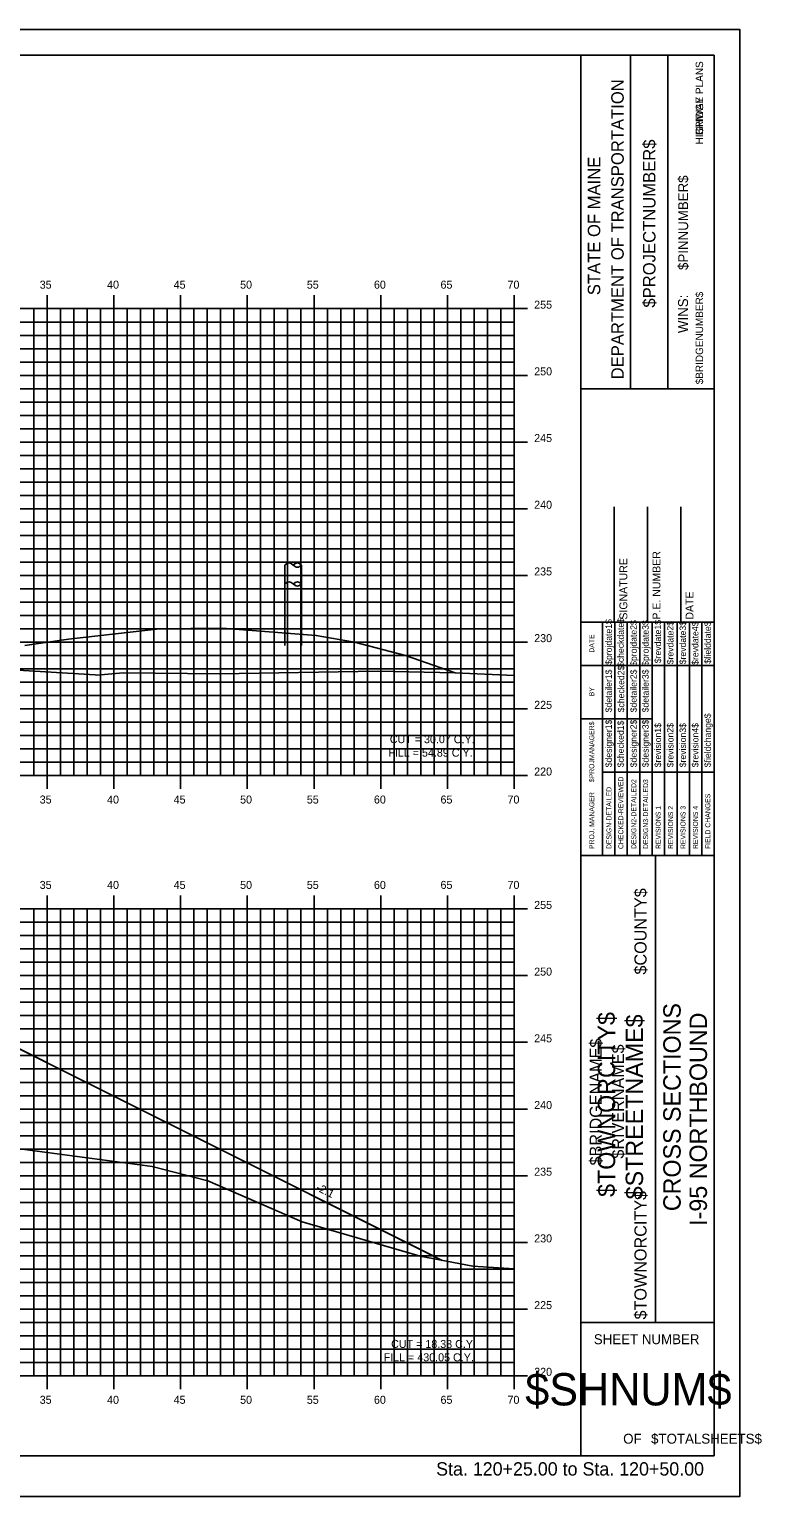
# Model space of a CAD drawing. Extents: x -22 to 1480, y -1511 to 8.
# Drawn here: x 665.3 to 720.2, y -1511.4 to -1401.4 of the extents above; entities that cross this region are included whole.
import ezdxf

# ---------------------------------------------------------------- set-up
doc = ezdxf.new("R2010")
doc.units = 0
for name, color, linetype in [('ANNOTATION', 7, 'Continuous'), ('BORDER', 7, 'Continuous'), ('BRIDGE_TITLE', 7, 'Continuous'), ('D_Roadway_Centerline', 7, 'Continuous'), ('D_Roadway_SlopeLines', 7, 'Continuous'), ('H_V ANNOTATION', 7, 'Continuous'), ('HIGHWAY_TITLE', 7, 'Continuous'), ('MAJOR', 7, 'Continuous'), ('MINOR', 7, 'Continuous'), ('PLOT BOUNDARY', 7, 'Continuous'), ('S_Roadway_Centerline', 7, 'Continuous'), ('S_Utilities_Pole_Joint', 7, 'Continuous'), ('S_Utilities_Pole_Power', 7, 'Continuous')]:
    doc.layers.add(name, color=color, linetype=linetype)

msp = doc.modelspace()

# ---------------------------------------------------------------- linework, layer by layer
at = {"layer": 'BORDER'}
for p, q in [((716.67, -1403.33), (556.67, -1403.33)), ((706.67, -1508.33), (706.67, -1403.33)), ((710.4, -1428.33), (710.4, -1403.33)), ((713.19, -1428.33), (713.19, -1403.33)), ((716.67, -1508.33), (716.67, -1403.33)), ((706.67, -1428.34), (716.67, -1428.34)), ((709.17, -1445.83), (709.17, -1437.18)), ((711.67, -1445.83), (711.67, -1437.18)), ((714.17, -1445.83), (714.17, -1437.18)), ((706.67, -1445.83), (716.67, -1445.83)), ((706.67, -1463.33), (716.67, -1463.33)), ((712.26, -1498.33), (712.26, -1463.33)), ((706.67, -1498.33), (716.67, -1498.33)), ((556.67, -1508.33), (716.67, -1508.33))]:
    msp.add_line(p, q, dxfattribs=at)
for points in [[(708.28, -1449.08), (708.28, -1445.83)], [(709.22, -1463.33), (709.22, -1445.83)], [(710.15, -1445.83), (710.15, -1463.33)], [(711.08, -1463.33), (711.08, -1445.83)], [(712.01, -1463.33), (712.01, -1445.83)], [(712.94, -1463.33), (712.94, -1445.83)], [(713.88, -1463.33), (713.88, -1445.83)], [(714.81, -1463.33), (714.81, -1445.83)], [(715.74, -1463.33), (715.74, -1445.83)], [(708.29, -1463.33), (708.29, -1446.53)], [(706.67, -1449.08), (716.67, -1449.08)], [(706.67, -1453.08), (708.29, -1453.08)], [(708.28, -1453.08), (712.01, -1453.08)], [(708.28, -1457.08), (716.67, -1457.08)]]:
    msp.add_lwpolyline(points, dxfattribs=at)
at = {"layer": 'D_Roadway_Centerline'}
for points in [[(665, -1447.57), (668.26, -1447.1), (675.1, -1446.33), (679.79, -1446.27), (686.84, -1446.83), (689.71, -1447.33), (693.52, -1448.33), (697.26, -1449.64)], [(606.5, -1475.8), (610.67, -1473.71), (613.67, -1473.59), (619.67, -1473.35), (631.67, -1473.11), (643.67, -1473.35), (653.67, -1473.75), (656.67, -1473.87), (662.65, -1476.86), (677.61, -1484.34), (694.96, -1493.02), (696.27, -1493.68)]]:
    msp.add_lwpolyline(points, dxfattribs=at)
at = {"layer": 'D_Roadway_SlopeLines'}
msp.add_lwpolyline([(656.67, -1473.87), (696.27, -1493.68)], dxfattribs=at)
at = {"layer": 'MAJOR'}
for p, q in [((666.67, -1421.33), (666.67, -1422.33)), ((671.67, -1421.33), (671.67, -1422.33)), ((676.67, -1421.33), (676.67, -1422.33)), ((681.67, -1421.33), (681.67, -1422.33)), ((686.67, -1421.33), (686.67, -1422.33)), ((691.67, -1421.33), (691.67, -1422.33)), ((696.67, -1421.33), (696.67, -1422.33)), ((701.67, -1421.33), (701.67, -1422.33)), ((561.67, -1422.33), (701.67, -1422.33)), ((561.67, -1422.33), (701.67, -1422.33)), ((666.67, -1457.33), (666.67, -1422.33)), ((671.67, -1457.33), (671.67, -1422.33)), ((676.67, -1457.33), (676.67, -1422.33)), ((681.67, -1457.33), (681.67, -1422.33)), ((686.67, -1457.33), (686.67, -1422.33)), ((691.67, -1457.33), (691.67, -1422.33)), ((696.67, -1457.33), (696.67, -1422.33)), ((702.67, -1422.33), (700.67, -1422.33)), ((701.67, -1457.33), (701.67, -1422.33)), ((701.67, -1457.33), (701.67, -1422.33)), ((561.67, -1427.33), (701.67, -1427.33)), ((702.67, -1427.33), (700.67, -1427.33)), ((561.67, -1432.33), (701.67, -1432.33)), ((702.67, -1432.33), (700.67, -1432.33)), ((561.67, -1437.33), (701.67, -1437.33)), ((702.67, -1437.33), (700.67, -1437.33)), ((561.67, -1442.33), (701.67, -1442.33)), ((702.67, -1442.33), (700.67, -1442.33)), ((561.67, -1447.33), (701.67, -1447.33)), ((702.67, -1447.33), (700.67, -1447.33)), ((561.67, -1452.33), (701.67, -1452.33)), ((702.67, -1452.33), (700.67, -1452.33)), ((561.67, -1457.33), (701.67, -1457.33)), ((561.67, -1457.33), (701.67, -1457.33)), ((666.67, -1458.33), (666.67, -1457.33)), ((671.67, -1458.33), (671.67, -1457.33)), ((676.67, -1458.33), (676.67, -1457.33)), ((681.67, -1458.33), (681.67, -1457.33)), ((686.67, -1458.33), (686.67, -1457.33)), ((691.67, -1458.33), (691.67, -1457.33)), ((696.67, -1458.33), (696.67, -1457.33)), ((702.67, -1457.33), (700.67, -1457.33)), ((701.67, -1458.33), (701.67, -1457.33)), ((561.67, -1467.33), (701.67, -1467.33)), ((561.67, -1467.33), (701.67, -1467.33)), ((666.67, -1466.33), (666.67, -1467.33)), ((666.67, -1502.33), (666.67, -1467.33)), ((671.67, -1466.33), (671.67, -1467.33)), ((671.67, -1502.33), (671.67, -1467.33)), ((676.67, -1466.33), (676.67, -1467.33)), ((676.67, -1502.33), (676.67, -1467.33)), ((681.67, -1466.33), (681.67, -1467.33)), ((681.67, -1502.33), (681.67, -1467.33)), ((686.67, -1466.33), (686.67, -1467.33)), ((686.67, -1502.33), (686.67, -1467.33)), ((691.67, -1466.33), (691.67, -1467.33)), ((691.67, -1502.33), (691.67, -1467.33)), ((696.67, -1466.33), (696.67, -1467.33)), ((696.67, -1502.33), (696.67, -1467.33)), ((702.67, -1467.33), (700.67, -1467.33)), ((701.67, -1466.33), (701.67, -1467.33)), ((701.67, -1502.33), (701.67, -1467.33)), ((701.67, -1502.33), (701.67, -1467.33)), ((561.67, -1472.33), (701.67, -1472.33)), ((702.67, -1472.33), (700.67, -1472.33)), ((561.67, -1477.33), (701.67, -1477.33)), ((702.67, -1477.33), (700.67, -1477.33)), ((561.67, -1482.33), (701.67, -1482.33)), ((702.67, -1482.33), (700.67, -1482.33)), ((561.67, -1487.33), (701.67, -1487.33)), ((702.67, -1487.33), (700.67, -1487.33)), ((561.67, -1492.33), (701.67, -1492.33)), ((702.67, -1492.33), (700.67, -1492.33)), ((561.67, -1497.33), (701.67, -1497.33)), ((702.67, -1497.33), (700.67, -1497.33)), ((561.67, -1502.33), (701.67, -1502.33)), ((561.67, -1502.33), (701.67, -1502.33)), ((666.67, -1503.33), (666.67, -1502.33)), ((671.67, -1503.33), (671.67, -1502.33)), ((676.67, -1503.33), (676.67, -1502.33)), ((681.67, -1503.33), (681.67, -1502.33)), ((686.67, -1503.33), (686.67, -1502.33)), ((691.67, -1503.33), (691.67, -1502.33)), ((696.67, -1503.33), (696.67, -1502.33)), ((702.67, -1502.33), (700.67, -1502.33)), ((701.67, -1503.33), (701.67, -1502.33))]:
    msp.add_line(p, q, dxfattribs=at)
at = {"layer": 'MINOR'}
for p, q in [((561.67, -1423.33), (701.67, -1423.33)), ((665.67, -1457.33), (665.67, -1422.33)), ((667.67, -1457.33), (667.67, -1422.33)), ((668.67, -1457.33), (668.67, -1422.33)), ((669.67, -1457.33), (669.67, -1422.33)), ((670.67, -1457.33), (670.67, -1422.33)), ((672.67, -1457.33), (672.67, -1422.33)), ((673.67, -1457.33), (673.67, -1422.33)), ((674.67, -1457.33), (674.67, -1422.33)), ((675.67, -1457.33), (675.67, -1422.33)), ((677.67, -1457.33), (677.67, -1422.33)), ((678.67, -1457.33), (678.67, -1422.33)), ((679.67, -1457.33), (679.67, -1422.33)), ((680.67, -1457.33), (680.67, -1422.33)), ((682.67, -1457.33), (682.67, -1422.33)), ((683.67, -1457.33), (683.67, -1422.33)), ((684.67, -1457.33), (684.67, -1422.33)), ((685.67, -1457.33), (685.67, -1422.33)), ((687.67, -1457.33), (687.67, -1422.33)), ((688.67, -1457.33), (688.67, -1422.33)), ((689.67, -1457.33), (689.67, -1422.33)), ((690.67, -1457.33), (690.67, -1422.33)), ((692.67, -1457.33), (692.67, -1422.33)), ((693.67, -1457.33), (693.67, -1422.33)), ((694.67, -1457.33), (694.67, -1422.33)), ((695.67, -1457.33), (695.67, -1422.33)), ((697.67, -1457.33), (697.67, -1422.33)), ((698.67, -1457.33), (698.67, -1422.33)), ((699.67, -1457.33), (699.67, -1422.33)), ((700.67, -1457.33), (700.67, -1422.33)), ((701.67, -1423.33), (700.67, -1423.33)), ((561.67, -1424.33), (701.67, -1424.33)), ((701.67, -1424.33), (700.67, -1424.33)), ((561.67, -1425.33), (701.67, -1425.33)), ((701.67, -1425.33), (700.67, -1425.33)), ((561.67, -1426.33), (701.67, -1426.33)), ((701.67, -1426.33), (700.67, -1426.33)), ((561.67, -1428.33), (701.67, -1428.33)), ((701.67, -1428.33), (700.67, -1428.33)), ((561.67, -1429.33), (701.67, -1429.33)), ((701.67, -1429.33), (700.67, -1429.33)), ((561.67, -1430.33), (701.67, -1430.33)), ((701.67, -1430.33), (700.67, -1430.33)), ((561.67, -1431.33), (701.67, -1431.33)), ((701.67, -1431.33), (700.67, -1431.33)), ((561.67, -1433.33), (701.67, -1433.33)), ((561.67, -1434.33), (701.67, -1434.33)), ((701.67, -1433.33), (700.67, -1433.33)), ((701.67, -1434.33), (700.67, -1434.33)), ((561.67, -1435.33), (701.67, -1435.33)), ((701.67, -1435.33), (700.67, -1435.33)), ((561.67, -1436.33), (701.67, -1436.33)), ((701.67, -1436.33), (700.67, -1436.33)), ((561.67, -1438.33), (701.67, -1438.33)), ((701.67, -1438.33), (700.67, -1438.33)), ((561.67, -1439.33), (701.67, -1439.33)), ((701.67, -1439.33), (700.67, -1439.33)), ((561.67, -1440.33), (701.67, -1440.33)), ((701.67, -1440.33), (700.67, -1440.33)), ((561.67, -1441.33), (701.67, -1441.33)), ((701.67, -1441.33), (700.67, -1441.33)), ((561.67, -1443.33), (701.67, -1443.33)), ((701.67, -1443.33), (700.67, -1443.33)), ((561.67, -1444.33), (701.67, -1444.33)), ((561.67, -1445.33), (701.67, -1445.33)), ((701.67, -1444.33), (700.67, -1444.33)), ((701.67, -1445.33), (700.67, -1445.33)), ((561.67, -1446.33), (701.67, -1446.33)), ((701.67, -1446.33), (700.67, -1446.33)), ((561.67, -1448.33), (701.67, -1448.33)), ((701.67, -1448.33), (700.67, -1448.33)), ((561.67, -1449.33), (701.67, -1449.33)), ((701.67, -1449.33), (700.67, -1449.33)), ((561.67, -1450.33), (701.67, -1450.33)), ((701.67, -1450.33), (700.67, -1450.33)), ((561.67, -1451.33), (701.67, -1451.33)), ((701.67, -1451.33), (700.67, -1451.33)), ((561.67, -1453.33), (701.67, -1453.33)), ((701.67, -1453.33), (700.67, -1453.33)), ((561.67, -1454.33), (701.67, -1454.33)), ((701.67, -1454.33), (700.67, -1454.33)), ((561.67, -1455.33), (701.67, -1455.33)), ((561.67, -1456.33), (701.67, -1456.33)), ((701.67, -1455.33), (700.67, -1455.33)), ((701.67, -1456.33), (700.67, -1456.33)), ((665.67, -1502.33), (665.67, -1467.33)), ((667.67, -1502.33), (667.67, -1467.33)), ((668.67, -1502.33), (668.67, -1467.33)), ((669.67, -1502.33), (669.67, -1467.33)), ((670.67, -1502.33), (670.67, -1467.33)), ((672.67, -1502.33), (672.67, -1467.33)), ((673.67, -1502.33), (673.67, -1467.33)), ((674.67, -1502.33), (674.67, -1467.33)), ((675.67, -1502.33), (675.67, -1467.33)), ((677.67, -1502.33), (677.67, -1467.33)), ((678.67, -1502.33), (678.67, -1467.33)), ((679.67, -1502.33), (679.67, -1467.33)), ((680.67, -1502.33), (680.67, -1467.33)), ((682.67, -1502.33), (682.67, -1467.33)), ((683.67, -1502.33), (683.67, -1467.33)), ((684.67, -1502.33), (684.67, -1467.33)), ((685.67, -1502.33), (685.67, -1467.33)), ((687.67, -1502.33), (687.67, -1467.33)), ((688.67, -1502.33), (688.67, -1467.33)), ((689.67, -1502.33), (689.67, -1467.33)), ((690.67, -1502.33), (690.67, -1467.33)), ((692.67, -1502.33), (692.67, -1467.33)), ((693.67, -1502.33), (693.67, -1467.33)), ((694.67, -1502.33), (694.67, -1467.33)), ((695.67, -1502.33), (695.67, -1467.33)), ((697.67, -1502.33), (697.67, -1467.33)), ((698.67, -1502.33), (698.67, -1467.33)), ((699.67, -1502.33), (699.67, -1467.33)), ((700.67, -1502.33), (700.67, -1467.33)), ((561.67, -1468.33), (701.67, -1468.33)), ((701.67, -1468.33), (700.67, -1468.33)), ((561.67, -1469.33), (701.67, -1469.33)), ((701.67, -1469.33), (700.67, -1469.33)), ((561.67, -1470.33), (701.67, -1470.33)), ((701.67, -1470.33), (700.67, -1470.33)), ((561.67, -1471.33), (701.67, -1471.33)), ((701.67, -1471.33), (700.67, -1471.33)), ((561.67, -1473.33), (701.67, -1473.33)), ((701.67, -1473.33), (700.67, -1473.33)), ((561.67, -1474.33), (701.67, -1474.33)), ((701.67, -1474.33), (700.67, -1474.33)), ((561.67, -1475.33), (701.67, -1475.33)), ((701.67, -1475.33), (700.67, -1475.33)), ((561.67, -1476.33), (701.67, -1476.33)), ((701.67, -1476.33), (700.67, -1476.33)), ((561.67, -1478.33), (701.67, -1478.33)), ((701.67, -1478.33), (700.67, -1478.33)), ((561.67, -1479.33), (701.67, -1479.33)), ((701.67, -1479.33), (700.67, -1479.33)), ((561.67, -1480.33), (701.67, -1480.33)), ((701.67, -1480.33), (700.67, -1480.33)), ((561.67, -1481.33), (701.67, -1481.33)), ((701.67, -1481.33), (700.67, -1481.33)), ((561.67, -1483.33), (701.67, -1483.33)), ((701.67, -1483.33), (700.67, -1483.33)), ((561.67, -1484.33), (701.67, -1484.33)), ((701.67, -1484.33), (700.67, -1484.33)), ((561.67, -1485.33), (701.67, -1485.33)), ((701.67, -1485.33), (700.67, -1485.33)), ((561.67, -1486.33), (701.67, -1486.33)), ((701.67, -1486.33), (700.67, -1486.33)), ((561.67, -1488.33), (701.67, -1488.33)), ((561.67, -1489.33), (701.67, -1489.33)), ((701.67, -1488.33), (700.67, -1488.33)), ((701.67, -1489.33), (700.67, -1489.33)), ((561.67, -1490.33), (701.67, -1490.33)), ((701.67, -1490.33), (700.67, -1490.33)), ((561.67, -1491.33), (701.67, -1491.33)), ((701.67, -1491.33), (700.67, -1491.33)), ((561.67, -1493.33), (701.67, -1493.33)), ((701.67, -1493.33), (700.67, -1493.33)), ((561.67, -1494.33), (701.67, -1494.33)), ((701.67, -1494.33), (700.67, -1494.33)), ((561.67, -1495.33), (701.67, -1495.33)), ((701.67, -1495.33), (700.67, -1495.33)), ((561.67, -1496.33), (701.67, -1496.33)), ((701.67, -1496.33), (700.67, -1496.33)), ((561.67, -1498.33), (701.67, -1498.33)), ((701.67, -1498.33), (700.67, -1498.33)), ((561.67, -1499.33), (701.67, -1499.33)), ((561.67, -1500.33), (701.67, -1500.33)), ((701.67, -1499.33), (700.67, -1499.33)), ((701.67, -1500.33), (700.67, -1500.33)), ((561.67, -1501.33), (701.67, -1501.33)), ((701.67, -1501.33), (700.67, -1501.33))]:
    msp.add_line(p, q, dxfattribs=at)
at = {"layer": 'PLOT BOUNDARY'}
msp.add_lwpolyline([(548.58, -1511.39), (718.58, -1511.39), (718.58, -1401.39), (548.58, -1401.39)], close=True, dxfattribs=at)
at = {"layer": 'S_Roadway_Centerline'}
for points in [[(657.85, -1449.04), (670.26, -1449.77), (670.4, -1449.8), (672.36, -1449.63), (679.59, -1449.71), (691.44, -1449.5), (697.26, -1449.64), (701.67, -1449.82)], [(657.85, -1449.04), (670.26, -1449.77), (670.4, -1449.8), (672.36, -1449.63), (679.59, -1449.71), (691.44, -1449.5), (697.26, -1449.64), (701.67, -1449.82)], [(663.67, -1485.18), (674.54, -1486.64), (678.7, -1487.72), (685.77, -1490.8), (694.62, -1493.36), (698.57, -1494.11), (701.67, -1494.32)], [(663.67, -1485.18), (674.54, -1486.64), (678.7, -1487.72), (685.77, -1490.8), (694.62, -1493.36), (698.57, -1494.11), (701.67, -1494.32)]]:
    msp.add_lwpolyline(points, dxfattribs=at)
at = {"layer": 'S_Utilities_Pole_Joint'}
for p, q in [((684.48, -1441.55), (684.64, -1441.44)), ((684.95, -1441.44), (685.1, -1441.55)), ((685.26, -1441.44), (685.1, -1441.55)), ((685.1, -1441.55), (685.26, -1441.66)), ((685.73, -1441.55), (685.57, -1441.44)), ((685.57, -1441.66), (685.73, -1441.55)), ((684.49, -1442.97), (684.64, -1442.86)), ((684.95, -1442.86), (685.11, -1442.97)), ((685.27, -1442.86), (685.11, -1442.97)), ((685.11, -1442.97), (685.27, -1443.08)), ((685.74, -1442.97), (685.58, -1442.86)), ((685.58, -1443.08), (685.74, -1442.97))]:
    msp.add_line(p, q, dxfattribs=at)
for centre, start, end in [((684.79, -1441.66), 90, 125.2644), ((684.79, -1441.66), 54.7356, 90), ((685.42, -1441.66), 90, 125.2644), ((685.42, -1441.44), 234.7356, 270), ((685.42, -1441.66), 54.7356, 90), ((685.42, -1441.44), 270, 305.2644), ((684.8, -1443.08), 90, 125.2644), ((684.8, -1443.08), 54.7356, 90), ((685.42, -1443.08), 90, 125.2644), ((685.42, -1442.86), 234.7356, 270), ((685.42, -1443.08), 54.7356, 90), ((685.42, -1442.86), 270, 305.2644)]:
    msp.add_arc(centre, 0.271, start, end, dxfattribs=at)
at = {"layer": 'S_Utilities_Pole_Power'}
for p, q in [((684.48, -1446.17), (684.48, -1441.55)), ((685.73, -1446.17), (685.73, -1441.55)), ((684.49, -1447.59), (684.48, -1442.97)), ((685.74, -1447.59), (685.73, -1442.97))]:
    msp.add_line(p, q, dxfattribs=at)

# ---------------------------------------------------------------- texts
at = {"layer": 'ANNOTATION'}
for s, rotation, p in [('CUT = 30.07 C.Y.', 359.9241, (692.35, -1454.9)), ('FILL = 54.89 C.Y.', 359.9241, (692.24, -1455.91)), ('-2:1', 333.4358, (686.76, -1488.4)), ('CUT = 18.38 C.Y.', 359.9241, (692.45, -1500.24)), ('FILL = 430.05 C.Y.', 359.9241, (691.89, -1501.24))]:
    msp.add_text(s, height=0.6, rotation=rotation, dxfattribs=at).set_placement(p)
at = {"layer": 'BORDER'}
for s, height, rotation, p in [('DEPARTMENT OF TRANSPORTATION', 0.9318, 90, (709.88, -1427.63)), ('$PROJECTNUMBER$', 0.9318, 90, (712.26, -1422.25)), ('STATE OF MAINE', 0.9318, 90, (708.12, -1421.32)), ('$PINNUMBER$', 0.7453, 90, (714.71, -1419.43)), ('WINS:', 0.745, 90, (714.7, -1424.16)), ('P.E. NUMBER', 0.5906, 90, (712.63, -1445.64)), ('SIGNATURE', 0.591, 90, (710.15, -1445.64)), ('DATE', 0.591, 90, (715.11, -1445.64)), ('$projdate1$', 0.4845, 90, (708.99, -1449.03)), ('$checkdate$', 0.4845, 90, (709.89, -1449.19)), ('$projdate2$', 0.4845, 90, (710.86, -1449.11)), ('$projdate3$', 0.4845, 90, (711.75, -1449.11)), ('$revdate1$', 0.485, 90, (712.68, -1448.91)), ('$revdate2$', 0.485, 90, (713.61, -1448.99)), ('$revdate3$', 0.485, 90, (714.55, -1448.99)), ('$revdate4$', 0.485, 90, (715.48, -1449.03)), ('$fielddate$', 0.4845, 90, (716.41, -1448.95)), ('DATE', 0.371, 90, (707.67, -1448.12)), ('$detailer1$', 0.4845, 90, (708.99, -1452.59)), ('$checked2$', 0.485, 90, (709.92, -1452.59)), ('$detailer2$', 0.4845, 90, (710.86, -1452.59)), ('$detailer3$', 0.4845, 90, (711.75, -1452.59)), ('BY', 0.371, 90, (707.67, -1451.39)), ('$fieldchange$', 0.4845, 90, (716.41, -1456.71)), ('$PROJMANAGER$', 0.3727, 90, (707.67, -1457.83)), ('$designer1$', 0.4845, 90, (708.99, -1456.71)), ('$checked1$', 0.485, 90, (709.89, -1456.71)), ('$designer2$', 0.4845, 90, (710.86, -1456.71)), ('$designer3$', 0.4845, 90, (711.75, -1456.71)), ('$revision1$', 0.4845, 90, (712.68, -1456.71)), ('$revision2$', 0.4845, 90, (713.61, -1456.71)), ('$revision3$', 0.4845, 90, (714.55, -1456.71)), ('$revision4$', 0.4845, 90, (715.48, -1456.71)), ('DESIGN-DETAILED', 0.3727, 90, (708.96, -1462.84)), ('CHECKED-REVIEWED', 0.3727, 90, (709.85, -1462.84)), ('DESIGN2-DETAILED2', 0.3727, 90, (710.82, -1462.84)), ('DESIGN3-DETAILED3', 0.3727, 90, (711.71, -1462.84)), ('PROJ. MANAGER', 0.3727, 90, (707.67, -1462.84)), ('FIELD CHANGES', 0.3727, 90, (716.37, -1462.84)), ('REVISIONS 1', 0.3727, 90, (712.65, -1462.84)), ('REVISIONS 2', 0.3727, 90, (713.58, -1462.84)), ('REVISIONS 3', 0.3727, 90, (714.51, -1462.84)), ('REVISIONS 4', 0.3727, 90, (715.44, -1462.84)), ('CROSS SECTIONS', 1.3043, 90, (714.15, -1489.99)), ('I-95 NORTHBOUND', 1.3043, 90, (716.12, -1491.09)), ('SHEET NUMBER', 0.7453, 360, (707.64, -1499.96)), ('$SHNUM$', 2.419, 360, (702.5, -1504.55)), ('OF', 0.745, 360, (709.84, -1507.42)), ('$TOTALSHEETS$', 0.7453, 360, (711.93, -1507.42))]:
    msp.add_text(s, height=height, rotation=rotation, dxfattribs=at).set_placement(p)
at = {"layer": 'BRIDGE_TITLE'}
for s, height, p in [('BRIDGE PLANS', 0.559, (715.83, -1409.31)), ('$BRIDGENUMBER$', 0.559, (715.83, -1428)), ('$COUNTY$', 0.907, (711.59, -1472.25)), ('$BRIDGENAME$', 0.9072, (708.24, -1486.56)), ('$RIVERNAME$', 0.9072, (709.91, -1486.05)), ('$TOWNORCITY$', 0.9072, (711.59, -1498.11))]:
    msp.add_text(s, height=height, rotation=90, dxfattribs=at).set_placement(p)
at = {"layer": 'H_V ANNOTATION'}
for s, height, p in [('35', 0.6, (666.11, -1420.83)), ('40', 0.6, (671.16, -1420.83)), ('45', 0.6, (676.15, -1420.83)), ('50', 0.6, (681.13, -1420.83)), ('55', 0.6, (686.13, -1420.83)), ('60', 0.6, (691.16, -1420.83)), ('65', 0.6, (696.15, -1420.83)), ('70', 0.6, (701.17, -1420.83)), ('255', 0.6, (703.17, -1422.33)), ('250', 0.6, (703.17, -1427.33)), ('245', 0.6, (703.17, -1432.33)), ('240', 0.6, (703.17, -1437.33)), ('235', 0.6, (703.17, -1442.33)), ('230', 0.6, (703.17, -1447.33)), ('225', 0.6, (703.17, -1452.33)), ('220', 0.6, (703.17, -1457.33)), ('35', 0.6, (666.11, -1459.43)), ('40', 0.6, (671.16, -1459.43)), ('45', 0.6, (676.15, -1459.43)), ('50', 0.6, (681.13, -1459.43)), ('55', 0.6, (686.13, -1459.43)), ('60', 0.6, (691.16, -1459.43)), ('65', 0.6, (696.15, -1459.43)), ('70', 0.6, (701.17, -1459.43)), ('35', 0.6, (666.11, -1465.83)), ('40', 0.6, (671.16, -1465.83)), ('45', 0.6, (676.15, -1465.83)), ('50', 0.6, (681.13, -1465.83)), ('55', 0.6, (686.13, -1465.83)), ('60', 0.6, (691.16, -1465.83)), ('65', 0.6, (696.15, -1465.83)), ('70', 0.6, (701.17, -1465.83)), ('255', 0.6, (703.17, -1467.33)), ('250', 0.6, (703.17, -1472.33)), ('245', 0.6, (703.17, -1477.33)), ('240', 0.6, (703.17, -1482.33)), ('235', 0.6, (703.17, -1487.33)), ('230', 0.6, (703.17, -1492.33)), ('225', 0.6, (703.17, -1497.33)), ('220', 0.6, (703.17, -1502.33)), ('35', 0.6, (666.11, -1504.43)), ('40', 0.6, (671.16, -1504.43)), ('45', 0.6, (676.15, -1504.43)), ('50', 0.6, (681.13, -1504.43)), ('55', 0.6, (686.13, -1504.43)), ('60', 0.6, (691.16, -1504.43)), ('65', 0.6, (696.15, -1504.43)), ('70', 0.6, (701.17, -1504.43)), ('Sta. 120+25.00 to Sta. 120+50.00', 1.0002, (695.82, -1509.81))]:
    msp.add_text(s, height=height, dxfattribs=at).set_placement(p)
at = {"layer": 'HIGHWAY_TITLE'}
for s, height, p in [('HIGHWAY PLANS', 0.559, (715.83, -1410.02)), ('$TOWNORCITY$', 1.3043, (709.24, -1488.92)), ('$STREETNAME$', 1.3043, (711.33, -1489.1))]:
    msp.add_text(s, height=height, rotation=90, dxfattribs=at).set_placement(p)

doc.saveas('drawing.dxf')
